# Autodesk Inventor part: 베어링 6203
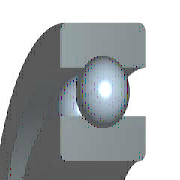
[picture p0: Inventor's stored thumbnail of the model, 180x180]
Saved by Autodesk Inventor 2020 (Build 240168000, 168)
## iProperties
IsCustomPart: 0
Created: 2016-04
Part Number: 베어링 6203
Material: 강철, 연강
Description: 깊은 그루브 볼 베어링
Document SubType Name: Modeling
Standard: KS B 2023
Designer: mdu
Standards Organization: KS
Language: ko-KR
Size Designation: 6203 - 17 x 40 x 12
Categories: <MemberInstance><Categories><Category DisplayName="샤프트 부품" InternalName="7f7aeb1f-a693-4053-b835-cee3144e0d98" Mnemonic="SHFT"><Category DisplayName="베어링" Inter
Density: 7.86 g/cm^3
Mass: 64.9809 g
Surface Area: 64.3582 cm^2
Volume: 8.26729 cm^3
Appearance: 노란색
Author: mdu
Revision Number: 1
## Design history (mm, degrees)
sketch "스케치" dims "d0" = 5.98 (= -0.26 x WD + 0.26 x BD)
  geometry: L1 (3.01, 14.25)-(8.99, 14.25); L2 (6, 14.25)-(6, 11.26); L3 (6, 14.25)-(6, 17.24); L4 (3.778, 12.249)-(0, 12.249); L5 (0, 8.5)-(12, 8.5); L6 (3.778, 16.251)-(0, 16.251); L7 (0, 20)-(12, 20); L8 (12, 8.5)-(12, 12.249); L9 (8.222, 12.249)-(12, 12.249); L10 (8.222, 16.251)-(12, 16.251); L11 (12, 20)-(12, 16.251); L12 (-1.4, 0)-(8.4, 0) reference; L13 (0, -0.3)-(0, 5.3) reference
  constraints: 22 end point, 4 point on line, 2 collinear, 2 perpendicular, 2 symmetric about line, 1 midpoint, 1 parallel, 14 other
  dimensions: "d9" = 17 diameter of L5 L12 (= WD); "d11" = 40 diameter of L7 L12 (= BD); "d12" = 12 distance between parallel lines of L8 L13 (= KB); "d13" = 24.498 diameter of L9 L12 (= 0.326 x BD + 0.674 x WD)
revolve "본체" stored, may be unused: angle "d6" = 90 deg
revolve "볼" stored, may be unused: angle "d7" = 90 deg
pattern_circular "IDS_ARRAYBALL[SIMPL:T]" dims angle "d3" = 360 deg
body "Solid1"
fillet "모깎기1" dims "d1" = 0.6 (= KRS)
other parameters: "WD" = 17 [user parameter; used in 5 equation terms], "BD" = 40 [user parameter; used in 5 equation terms], "KB" = 12 [user parameter; used in 1 equation term], "KRS" = 0.6 [user parameter; used in 1 equation term], "d4" = 0, "d5" = 0, "d8" = 0, "d14" = 0, "d15" = 0, "BBA" = 0 [user parameter], "BC0" = 4750000 [user parameter], "BC" = 9560000 [user parameter], "WR" = 8.5 (= 0.5 x WD) [user parameter]
